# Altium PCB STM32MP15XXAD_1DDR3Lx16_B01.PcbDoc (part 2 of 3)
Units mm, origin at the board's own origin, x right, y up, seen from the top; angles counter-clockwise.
Board outline 86 x 120 mm, 4 copper layers (Top Layer, Signal Layer 1, Signal Layer 2, Bottom Layer), stack 1.571 mm thick; 118 components, 119 nets, 781 pads, 336 vias.
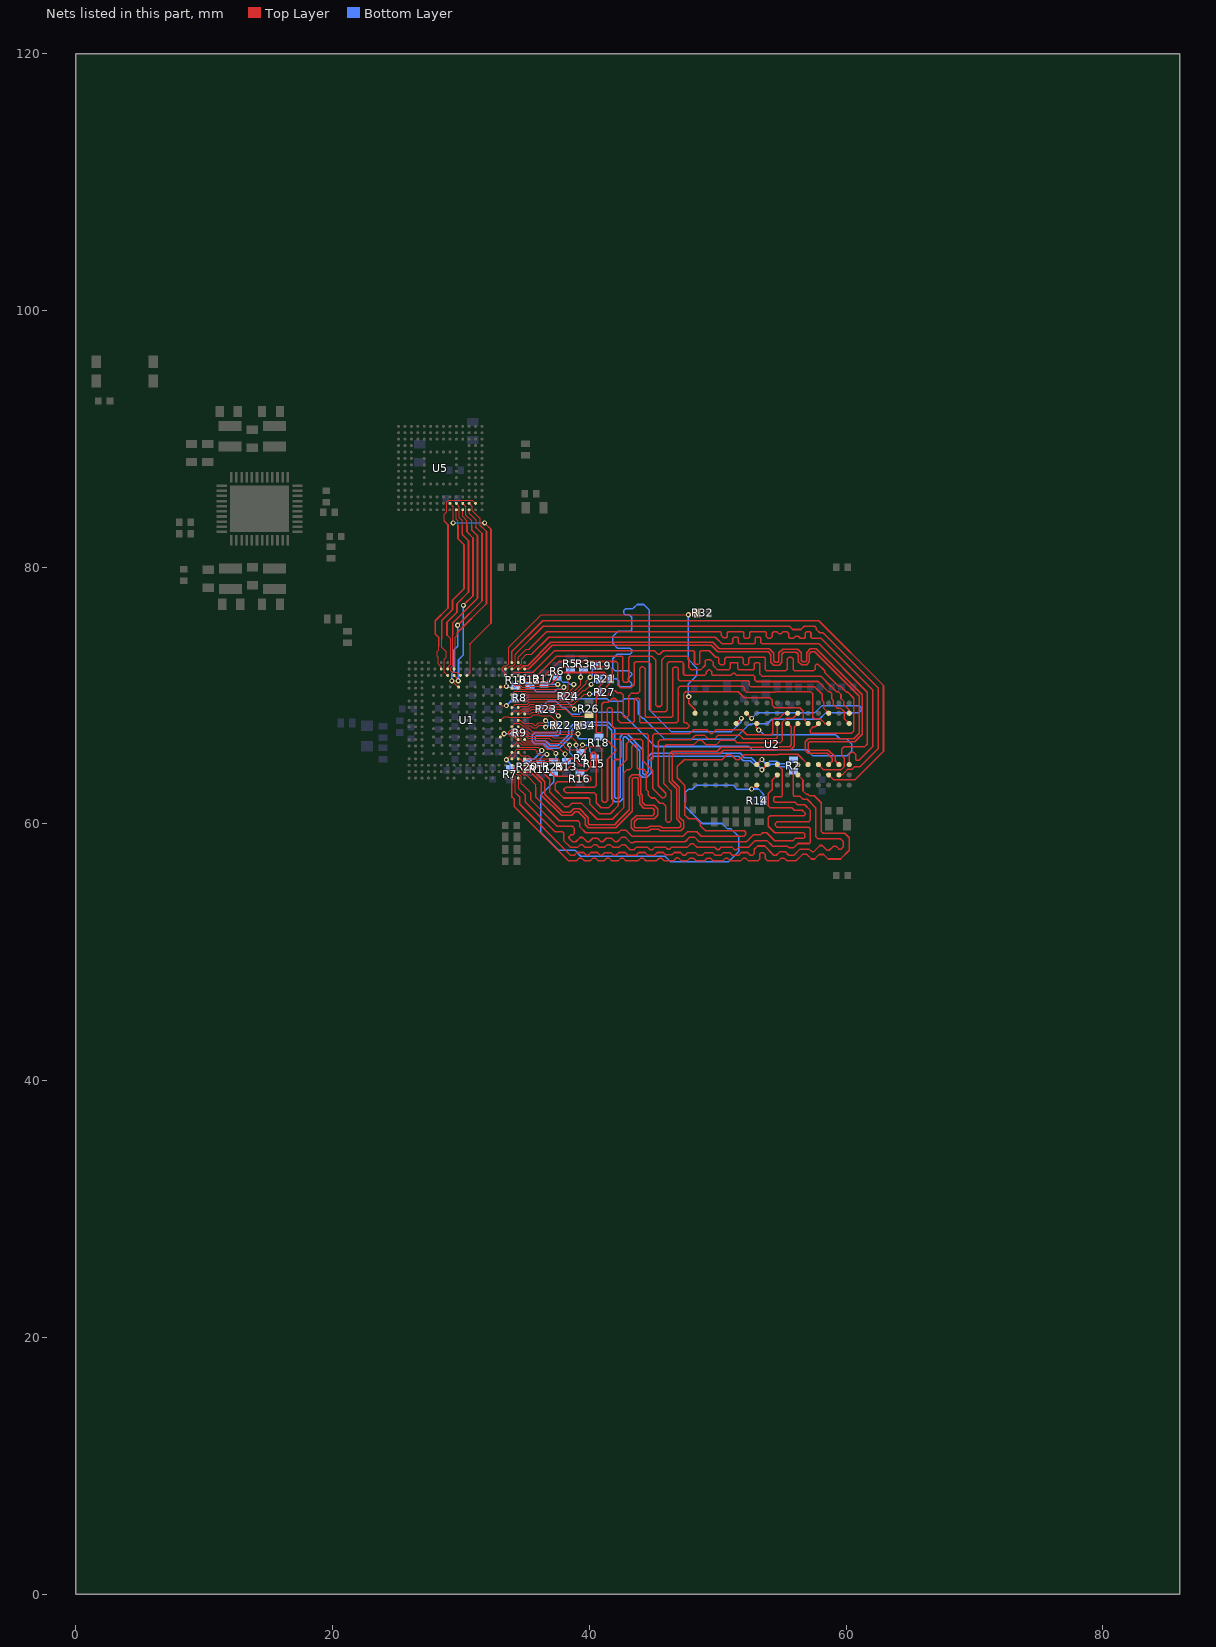
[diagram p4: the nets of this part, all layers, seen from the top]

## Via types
v1: diameter 0.4, hole 0.2, Top Layer to Bottom Layer, tented both sides, 260 vias
v2: diameter 0.6, hole 0.3, Top Layer to Bottom Layer, tented both sides, 74 vias
v3: diameter 0.4, hole 0.2, Top Layer to Signal Layer 1, tented top, 2 vias

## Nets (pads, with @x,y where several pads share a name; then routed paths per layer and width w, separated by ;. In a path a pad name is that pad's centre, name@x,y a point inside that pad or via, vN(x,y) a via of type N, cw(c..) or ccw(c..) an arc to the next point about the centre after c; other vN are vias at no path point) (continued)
BA2: R21.2 U2.M3 | length 32.5
  Top Layer w0.12: U2.M3@51.45,67.825 v1@51.83,68.205
  Bottom Layer w0.12: R21.2@41.675,71.3 42.15,71.3 42.3,71.15 42.3,70.82 42.425,70.695 43.201,70.695 43.305,70.799 43.305,70.945 43.05,71.2 43.05,71.35 43.305,71.605 43.305,71.72 43.1,71.925 42,71.925 41.825,72.1 41.825,72.869 42.176,73.22 43.175,73.22 43.305,73.35 43.305,73.57 43.2,73.675 42.226,73.675 41.825,74.076 41.825,74.594 42.226,74.995 43.175,74.995 43.305,75.125 43.305,76.1 43.11,76.295 42.805,76.295 42.7,76.4 42.7,76.65 42.8,76.75 43.375,76.75 43.5,76.875 ; 43.503,76.872 43.726,77.095 44.249,77.095 44.66,76.684 44.66,68.915 46.38,67.195 47.823,67.195 47.828,67.2 51.085,67.2 51.85,67.965 v1(51.85,68.225)
CASN: R23.2 U2.K3 | length 35.4
  Top Layer w0.12: U2.K3@53.05,67.825 53.025,67.8 53.025,67.5 v1@53.2,67.325
  Bottom Layer w0.12: R23.2@36.2,68.95 36.2,68.975 36.8,69.575 37.4,69.575 37.938,69.037 38.137,69.037 38.585,68.59 38.645,68.53 39.181,68.53 39.362,68.714 39.368,68.72 42.455,68.72 42.55,68.625 45.14,66.035 52.44,66.035 52.685,65.79 56.935,65.79 57.395,65.33 60.099,65.33 60.445,65.676 60.445,66.23 60.03,66.645 59.505,66.645 59.275,66.875 59.185,66.965 53.585,66.965 53.225,67.325 53.205,67.325 v1(53.2,67.32)
CKE: R14.2 R25.2 U2.K9 | length 36.9
  Top Layer w0.09: v1(52.65,62.725) 52.7,62.725 U2.K9@53,63.025
  Top Layer w0.1: U2.K9@53.05,63.025 U2.K9@53.075,63.025
  Top Layer w0.12: U2.K9@53,63.025 U2.K9@53.05,63.025
  Bottom Layer w0.12: R25.2@37.225,64 37.225,63.257 36.225,62.257 36.225,59.337 37.624,57.939 38.906,57.939 39.349,57.495 45.904,57.495 46.324,57.075 50.863,57.075 51.64,57.852 51.64,59.023 51.048,59.615 50.767,59.615 50.342,60.04 48.802,60.04 47.45,61.392 47.45,62.434 47.726,62.71 48.032,62.71 48.357,63.035 51.19,63.035 51.512,62.713 52.637,62.713 v1(52.65,62.725) 53.175,62.725 53.575,62.325 53.575,61.825 R14.2@53.575,61.775
CSN: R24.2 U2.L2 | length 35.3
  Top Layer w0.12: U2.L2@52.25,68.625 v1(52.65,68.225)
  Bottom Layer w0.12: R24.2@38.775,69.95 R24.2@38.8,69.95 38.875,69.95 39.075,69.75 41.384,69.75 41.574,69.56 42.56,69.56 42.75,69.75 43.6,69.75 43.805,69.545 43.805,68.576 44.153,68.228 ; 44.15,68.225 44.25,68.225 45.86,66.615 51.315,66.615 52.45,67.75 52.675,67.75 52.725,67.8 53.875,67.8 54.225,68.15 57.925,68.15 58.45,68.675 61.025,68.675 61.175,68.825 61.175,69.1 61.05,69.225 58.125,69.225 57.55,68.65 53.075,68.65 v1(52.65,68.225)
DDR_A0: R3.1 U1.G18 | length 6.7
  Top Layer w0.09: U1.G18@34.46,69.58 34.465,69.585 34.705,69.825 35.125,69.825 35.205,69.905 38.38,69.905 39.325,70.85 v1(39.325,71.425)
  Bottom Layer w0.12: v1(39.325,71.425) 39.325,71.8 R3.1@39.55,72.025
DDR_A1: R4.1 U1.M19 | length 5.3
  Top Layer w0.09: U1.M19@34.975,67.075 35.075,67.075 35.3,66.85 37.1,66.85 37.225,66.725 38.675,66.725 38.975,66.425 v1(38.975,66.15)
  Bottom Layer w0.12: v1(38.975,66.15) 38.975,65.95 39.363,65.563 R4.1@39.375,65.55
DDR_A2: R5.1 U1.F17 | length 6.2
  Top Layer w0.09: U1.F17@33.96,70.08 33.965,70.085 34.2,70.32 35.076,70.32 35.096,70.3 37.865,70.3 ; 37.875,70.3 38.163,70.3 38.37,70.507 v1@38.37,71.425
  Bottom Layer w0.12: v1@38.35,71.425 38.362,71.438 38.375,71.45 38.375,71.9 R5.1@38.525,72.05
  other v1: 38.375,71.425
DDR_A3: R6.1 U1.F19 | length 5.8
  Top Layer w0.09: U1.F19@34.99,70.1 34.995,70.095 35.015,70.075 38.24,70.075 38.8,70.635 v1(38.8,70.875) v1@38.8,70.9
  Bottom Layer w0.12: R6.1@37.525,71.45 37.925,71.05 38.325,71.05 38.5,70.875 v1(38.8,70.875)
DDR_A4: R7.1 U1.R17 | length 1.6
  Top Layer w0.09: v1(33.55,65) 33.975,65.425 U1.R17@33.975,65.575
  Bottom Layer w0.1: R7.1@33.8,64.375 R7.1@33.85,64.325
  Bottom Layer w0.12: v1(33.55,65) 33.85,64.7 R7.1@33.85,64.325
DDR_A5: R8.1 U1.1C9 | length 1.5
  Top Layer w0.09: U1.1C9@33.075,69.375 33.225,69.225 v1(33.55,69.225)
  Top Layer w0.1: v1@33.45,69.325 v1(33.55,69.225)
  Bottom Layer w0.1: v1(33.55,69.225) R8.1@34.15,69.825
DDR_A6: R9.1 U1.1G9 | length 1.2
  Top Layer w0.09: U1.1G9@33.125,66.725 33.125,66.775 v1(33.375,67.025)
  Bottom Layer w0.1: v1(33.375,67.025) R9.1@34.15,67.025
DDR_A7: R10.1 U1.1A9 | length 1.3
  Top Layer w0.09: U1.1A9@33.075,70.675 33.5,70.675 v1(33.55,70.725)
  Bottom Layer w0.12: v1(33.55,70.725) 33.625,70.65 34.2,70.65 R10.1@34.3,70.75
DDR_A8: R11.1 U1.T17 | length 4.6
  Top Layer w0.09: U1.T17@33.975,65.075 34.222,65.322 34.222,65.678 34.364,65.82 35.743,65.82 35.945,65.618 35.945,65.48 36.045,65.38 36.655,65.38 v1(36.7,65.425)
  Bottom Layer w0.12: R11.1@36.2,64.7 36.2,65.1 36.525,65.425 v1(36.7,65.425)
DDR_A9: R12.1 U1.E18 | length 6.7
  Top Layer w0.09: U1.E18@34.46,70.58 34.475,70.58 34.633,70.58 34.723,70.49 37.865,70.49 v1(38.025,70.65)
  Bottom Layer w0.12: R12.1@35.4,70.8 35.9,70.3 37.3,70.3 37.5,70.5 37.875,70.5 v1(38.025,70.65) v1@38.05,70.675
DDR_A10: R13.1 U1.M17 | length 5.6
  Top Layer w0.09: U1.M17@33.97,67.08 33.975,67.08 34.116,67.08 34.366,66.83 34.585,66.83 34.72,66.695 34.72,66.484 34.874,66.33 36.545,66.33 36.8,66.075 37.5,66.075 v1@38.112,65.463 ; v1@38.031,65.556 38.088,65.5 v1@38.1,65.5
  Bottom Layer w0.12: v1(38.125,65.45) 38.125,65.025 R13.1@38.25,64.9
DDR_A11: R15.1 U1.N19 | length 6.6
  Top Layer w0.09: U1.N19@34.97,66.58 U1.N19@34.975,66.575 35.05,66.5 36.55,66.5 ; 36.555,66.5 36.7,66.5 36.925,66.275 37.813,66.275 38.288,65.8 39.175,65.8 39.45,66.075 v1@39.45,66.125
  Bottom Layer w0.12: v1(39.475,66.15) 39.825,66.15 40.03,65.945 40.03,65.676 40.4,65.306 R15.1@40.4,65.15 R15.1@40.4,65.125
DDR_A12: R16.1 U1.M18 | length 6.8
  Top Layer w0.09: U1.M18@34.47,67.08 34.475,67.08 34.624,67.08 34.884,66.82 35.08,66.82 35.225,66.675 36.9,66.675 37.075,66.5 38.125,66.5 v1(38.475,66.15) v1@38.5,66.125
  Bottom Layer w0.12: v1(38.475,66.15) 38.475,65.575 38.825,65.225 38.825,64.35 R16.1@39.15,64.025
DDR_A13: R17.1 U1.E17 | length 5
  Top Layer w0.09: U1.E17@33.96,70.58 33.965,70.585 34.205,70.825 34.628,70.825 34.793,70.66 35.385,70.66 35.45,70.725 37.4,70.725 v1(37.55,70.875)
  Bottom Layer w0.12: R17.1@36.5,70.875 v1(37.55,70.875) 37.585,70.875 v1@37.6,70.89
DDR_A14: R18.1 U1.N18 | length 8.7
  Top Layer w0.09: U1.N18@34.47,66.58 34.34,66.58 34.09,66.83 33.865,66.83 33.72,66.975 33.72,67.19 33.85,67.32 34.576,67.32 34.621,67.275 34.829,67.275 34.874,67.32 35.076,67.32 35.371,67.025 37.35,67.025 37.4,66.975 38.775,66.975 38.825,67.025 v1(39.125,67.025)
  Bottom Layer w0.12: v1(39.125,67.025) 39.125,66.725 39.2,66.65 R18.1@40.725,66.65
DDR_A15: R34.1 U1.L18 | length 5.2
  Top Layer w0.09: U1.L18@34.475,67.575 34.56,67.49 35.285,67.49 ; 35.295,67.48 35.575,67.2 38.725,67.2 38.813,67.288 38.813,67.588 38.9,67.675 R34.1@39.2,67.675
DDR_BA0: R19.1 U1.G19 | length 7
  Top Layer w0.09: U1.G19@34.96,69.58 34.975,69.58 35.18,69.58 35.325,69.725 38.525,69.725 39.75,70.95 39.75,71.1 v1(40.075,71.425)
  Bottom Layer w0.12: v1(40.075,71.425) 40.25,71.6 40.25,72.075 40.45,72.275 R19.1@40.45,72.325
DDR_BA1: R20.1 U1.P18 | length 3.5
  Top Layer w0.09: U1.P18@34.47,66.08 U1.P18@34.475,66.075 34.56,65.99 36.035,65.99 v1(36.3,65.725)
  Bottom Layer w0.12: R20.1@35.2,64.9 35.35,65.05 35.684,65.05 36.3,65.666 v1(36.3,65.725)
DDR_BA2: R21.1 U1.H17 | length 7.7
  Top Layer w0.09: U1.H17@33.975,69.075 34.23,69.33 35.17,69.33 35.365,69.525 38.65,69.525 39.525,70.4 39.7,70.4 40.125,70.825 v1@40.125,70.875
  Bottom Layer w0.12: v1@40.15,70.9 40.35,71.1 40.575,71.1 R21.1@40.775,71.3
  other v1: 40.15,70.875
DDR_CASN: R23.1 U1.J19 | length 3.6
  Top Layer w0.09: U1.J19@34.97,68.58 34.975,68.58 35.405,68.58 35.545,68.72 37.355,68.72 37.6,68.475 v1(37.6,68.425)
  Bottom Layer w0.12: R23.1@37.1,68.95 37.1,68.925 v1(37.6,68.425)
DDR_CKE: R25.1 U1.P17 | length 4.6
  Top Layer w0.09: U1.P17@33.95,66.08 33.975,66.08 34.116,66.08 34.366,66.33 34.595,66.33 34.765,66.16 36.365,66.16 36.7,65.825 37.075,65.825 v1(37.4,65.5)
  Bottom Layer w0.12: R25.1@37.225,64.875 R25.1@37.225,64.9 37.4,65.075 v1(37.4,65.5)
DDR_CLK_N: R2.1 U1.K18 U2.K7 | length 43.4
  Top Layer w0.09: U1.K18@34.475,68.075 34.625,68.075 34.87,67.83 35.57,67.83 35.7,67.7 35.856,67.7 36.046,67.89 36.44,67.89 v1(36.6,68.05)
  Top Layer w0.1: U2.K7@53.05,64.625 v1(53.45,65.025)
  Bottom Layer w0.1: v1(36.6,68.05) 36.675,68.05 36.82,67.905 37.52,67.905 37.755,67.67 37.755,67.08 37.55,66.875 35.85,66.875 35.78,66.805 35.78,66.545 35.845,66.48 36.57,66.48 36.91,66.14 37.59,66.14 38.42,66.97 38.42,67.395 38.775,67.75 39.55,67.75 39.73,67.93 41.47,67.93 42,67.4 42,62.075 42.07,62.005 42.305,62.005 42.4,62.1 42.4,66.8 42.63,67.03 42.945,67.03 44.175,65.8 44.175,63.95 44.27,63.855 44.38,63.855 44.61,64.085 44.61,65.235 44.88,65.505 51.745,65.505 52.088,65.163 52.637,65.163 53.05,64.75 53.175,64.75 v1(53.45,65.025) 53.725,64.75 53.925,64.75 54.05,64.875 54.625,64.875 54.825,64.675 55.5,64.675 R2.1@55.825,65
DDR_CLK_P: R2.2 U1.L17 U2.J7 | length 44.1
  Top Layer w0.09: U1.L17@33.97,67.58 34.22,67.83 34.601,67.83 34.771,67.66 35.45,67.66 35.61,67.5 35.925,67.5 36.125,67.7 36.45,67.7 v1(36.6,67.55)
  Top Layer w0.1: v1(53.45,64.225) U2.J7@53.85,64.625
  Bottom Layer w0.1: v1(36.6,67.55) 36.7,67.55 36.825,67.675 37.425,67.675 37.525,67.575 37.525,67.175 37.455,67.105 35.755,67.105 35.55,66.9 35.55,66.45 35.75,66.25 36.475,66.25 36.815,65.91 37.685,65.91 38.65,66.875 38.65,67.3 38.87,67.52 39.645,67.52 39.825,67.7 41.375,67.7 41.77,67.305 41.77,61.98 42,61.75 42.375,61.75 42.65,62.025 42.65,66.725 42.725,66.8 42.85,66.8 43.945,65.705 43.945,63.855 44.175,63.625 44.475,63.625 44.84,63.99 44.84,65.14 44.975,65.275 51.65,65.275 52,64.925 52.55,64.925 52.955,64.52 53.155,64.52 v1(53.45,64.225) 53.48,64.225 53.775,64.52 54.02,64.52 54.145,64.645 54.53,64.645 54.73,64.445 55,64.445 55.48,64.445 R2.2@55.825,64.1 ; R2.2@55.925,64.1 R2.2@55.925,64.175
DDR_CSN: R24.1 U1.J17 | length 6.6
  Top Layer w0.09: U1.J17@33.97,68.58 U1.J17@33.975,68.575 34.22,68.82 34.633,68.82 34.803,68.99 35.334,68.99 35.469,69.125 38.675,69.125 v1(38.85,68.95)
  Bottom Layer w0.12: R24.1@37.875,69.925 v1(38.85,68.95)
DDR_DQ0: U1.A17 U2.C8 | length 43.3
  Top Layer w0.12: U1.A17@33.975,72.575 33.975,73.425 36.375,75.825 57.877,75.825 62.92,70.782 62.92,65.67 60.7,63.45 59.025,63.45 U2.C8@58.65,63.825
DDR_DQ1: U1.A18 U2.A7 | length 42.3
  Top Layer w0.09: U1.A18@34.47,72.58 34.47,72.995 35.1,73.625 35.325,73.625
  Top Layer w0.12: 35.33,73.63 36.675,74.975 50.2,74.975 50.3,74.875 50.3,74.669 50.469,74.5 50.675,74.5 50.75,74.575 50.75,74.9 50.825,74.975 51.975,74.975 52.05,74.9 52.05,74.55 52.125,74.475 52.4,74.475 52.5,74.575 52.5,74.85 52.5,74.9 52.575,74.975 53.725,74.975 53.8,74.9 53.8,74.6 53.925,74.475 54.125,74.475 54.25,74.6 54.25,74.85 54.375,74.975 54.6,74.975 54.775,74.8 54.925,74.8 55.1,74.975 55.4,74.975 55.55,74.825 55.55,74.55 55.63,74.47 55.92,74.47 56.075,74.625 56.275,74.625 56.43,74.47 56.745,74.47 56.825,74.55 56.825,74.875 56.925,74.975 57.2,74.975 57.275,74.9 57.275,74.55 57.355,74.47 58.044,74.47 62.08,70.434 62.08,66.036 61.014,64.97 60.805,64.97 60.75,65.025 60.75,65.425 60.6,65.575 60.4,65.575 60.25,65.425 60.25,65.298 ; U2.A7@60.25,64.6 U2.A7@60.25,64.625 60.25,65.3
DDR_DQ2: U1.C18 U2.A3 | length 41.6
  Top Layer w0.09: U1.C18@34.47,71.58 U1.C18@34.475,71.575 34.72,71.33 36.315,71.33
  Top Layer w0.12: 36.329,71.346 37.638,72.655 42.095,72.655 42.205,72.545 42.205,70.845 42.425,70.625 43.275,70.625 43.5,70.85 43.5,72.525 43.625,72.65 44.625,72.65 44.78,72.495 44.78,68.87 44.925,68.725 45.925,68.725 46.07,68.87 46.07,72.495 46.225,72.65 47.225,72.65 47.345,72.53 47.345,71.655 47.425,71.575 48.975,71.575 49.1,71.7 49.1,71.825 49.275,72 49.4,72 49.55,71.85 49.55,71.65 49.625,71.575 50.025,71.575 51.025,71.575 51.2,71.75 51.325,71.75 51.5,71.575 52.8,71.575 52.899,71.476 52.899,71.226 53.025,71.1 57.831,71.1 58.646,70.285 58.765,70.285 ; 58.775,70.275 58.885,70.165 58.885,69.74 59.012,69.613 59.012,69.313 59.3,69.025 59.58,69.025 59.86,68.745 59.86,68.215 60.19,67.885 U2.A3@60.19,67.825
DDR_DQ3: U1.B16 U2.B8 | length 41.9
  Top Layer w0.09: U1.B16@33.47,72.08 33.475,72.08 33.55,72.08 33.55,72.106 33.528,72.128 33.52,72.136 33.661,72.136 33.845,72.32 34.076,72.32 34.078,72.318 34.225,72.465 34.225,73.2 34.3,73.275
  Top Layer w0.12: 34.3,73.275 36.425,75.4 55.6,75.4 55.85,75.15 56.5,75.15 56.75,75.4 57.575,75.4 57.7,75.275 57.7,75.15 57.95,74.9 58.175,74.9 ; 58.1,74.9 58.208,74.9 62.5,70.608 62.5,65.862 61.113,64.475 60.675,64.475 60.455,64.255 60.115,64.255 59.685,63.825 U2.B8@59.45,63.825
DDR_DQ4: U1.D18 U2.C3 | length 43.1
  Top Layer w0.09: U1.D18@34.47,71.08 34.475,71.08 34.614,71.08 34.864,70.83 35.155,70.83 35.25,70.925 37.075,70.925
  Top Layer w0.12: 37.075,70.95 37.925,71.8 41.2,71.8 41.35,71.65 41.35,71.275 40.55,70.475 40.55,67.175 40.625,67.1 40.9,67.1 40.975,67.175 40.975,69.325 41.125,69.475 41.5,69.475 41.8,69.775 42.025,69.775 42.23,69.57 42.23,68.095 42.45,67.875 43.375,67.875 43.5,68 43.5,69.7 43.575,69.775 43.85,69.775 43.925,69.7 43.925,67.975 44.02,67.88 46.805,67.88 46.925,68 46.925,68.688 46.925,70.575 47.075,70.725 51.975,70.725 52.059,70.641 52.059,70.441 52.25,70.25 54.475,70.25 54.51,70.285 57.265,70.285 57.41,70.14 57.41,68.315 57.525,68.2 57.984,68.2 58.359,67.825 U2.C3@58.65,67.825
DDR_DQ5: U1.D19 U2.C2 | length 43.4
  Top Layer w0.09: U1.D19@34.97,71.08 34.99,71.1 36.7,71.1
  Top Layer w0.12: 36.715,71.115 37.835,72.235 41.615,72.235 41.785,72.065 41.785,71.11 40.97,70.295 40.97,70.005 41.07,69.905 41.305,69.905 41.525,70.125 41.775,70.375 42.019,70.375 42.189,70.205 42.495,70.205 42.65,70.05 42.65,68.4 42.755,68.295 42.92,68.295 43.075,68.45 43.075,69.975 43.3,70.2 ; 43.306,70.206 43.3,70.2 ; 52.6,70.675 52.595,70.68 ; 57.42,70.68 57.425,70.68 ; U2.C2@58.65,68.625 58.25,69.025 58.25,69.525 58.15,69.625 58.15,70.1 57.57,70.68 57.358,70.68 52.595,70.68 ; 43.3,70.2 43.8,70.2 43.92,70.32 43.92,72.1 44.05,72.23 44.22,72.23 44.36,72.09 44.36,68.39 44.45,68.3 46.4,68.3 46.5,68.4 46.5,72.125 46.6,72.225 46.825,72.225 46.925,72.125 46.925,71.275 47.05,71.15 52.4,71.15 52.479,71.071 52.479,70.796 52.595,70.68
DDR_DQ6: U1.C19 U2.A2 | length 43.1
  Top Layer w0.09: U1.C19@34.96,71.58 34.975,71.58 35.98,71.58
  Top Layer w0.12: 35.982,71.593 37.464,73.075 42.55,73.075 42.625,73 42.625,71.15 42.73,71.045 42.97,71.045 43.075,71.15 43.075,71.425 ; 43.075,71.43 43.075,71.65 ; 43.075,71.655 43.075,72.875 ; 43.075,72.8 43.075,72.95 43.205,73.08 44.87,73.08 45.2,72.75 45.2,69.25 45.3,69.15 45.55,69.15 45.65,69.25 45.65,72.775 45.95,73.075 47.625,73.075 47.765,72.935 47.765,72.185 47.95,72 48.675,72 49.045,72.37 49.045,72.72 49.1,72.775 49.475,72.775 49.675,72.575 49.675,72.325 50,72 50.85,72 50.975,72.125 50.975,72.525 51.024,72.574 51.526,72.574 51.58,72.52 51.58,72.095 51.675,72 52.775,72 52.851,72.076 52.851,72.476 52.949,72.574 53.226,72.574 53.3,72.5 53.3,71.675 53.45,71.525 57.725,71.525 58.025,71.525 58.82,70.73 58.823,70.73 59.222,70.331 59.268,70.285 59.415,70.285 59.61,70.09 59.61,69.774 59.84,69.544 59.84,69.285 60.25,68.875 U2.A2@60.25,68.625
DDR_DQ7: U1.B17 U2.D7 | length 42.2
  Top Layer w0.09: U1.B17@33.97,72.08 33.975,72.08 34.115,72.08 34.365,72.33 34.58,72.33 34.73,72.48 34.73,72.843 35.112,73.225 35.5,73.225
  Top Layer w0.12: 35.525,73.231 36.844,74.55 49.825,74.55 50.325,74.05 51.1,74.05 51.175,74.125 51.175,74.45 51.275,74.55 51.55,74.55 51.625,74.475 51.625,74.125 51.7,74.05 52.85,74.05 52.925,74.125 52.925,74.475 53,74.55 53.3,74.55 53.375,74.475 53.375,74.125 53.45,74.05 57.87,74.05 61.66,70.26 61.66,66.21 61.45,66 59.825,66 59.675,65.85 59.675,65.325 59.83,65.17 ; U2.D7@57.85,64.625 58.26,64.215 59.62,64.215 59.85,64.445 59.85,65.17
DDR_DQ8: U1.R18 U2.E3 | length 43.4
  Top Layer w0.09: U1.R18@34.475,65.575 34.725,65.325 35.25,65.325 35.5,65.075 37.575,65.075 37.675,64.975
  Top Layer w0.12: 37.675,64.975 37.675,64.769 37.874,64.57 38,64.57 38.53,65.1 38.8,65.1 39.325,64.575 39.625,64.575 39.7,64.65 39.7,64.9 39.45,65.15 39.45,65.375 39.7,65.625 39.7,65.825 39.875,66 40.825,66 40.975,65.85 40.975,61.844 41.119,61.7 41.3,61.7 41.425,61.825 41.425,65.05 42.065,65.69 42.065,65.86 41.725,66.2 ; 41.75,66.175 41.4,66.525 41.4,68.95 41.505,69.055 41.705,69.055 41.81,68.95 41.81,67.59 41.95,67.45 47.637,67.45 47.775,67.588 47.775,67.7 47.6,67.875 47.425,67.875 47.35,67.95 47.35,68.519 47.35,70.125 47.525,70.3 51.6,70.3 52.075,69.825 54.08,69.825 54.24,69.665 54.24,69.26 54.445,69.055 56.395,69.055 56.665,68.785 56.665,68.21 U2.E3@57.05,67.825
DDR_DQ9: U1.U19 U2.F2 | length 42.9
  Top Layer w0.09: U1.U19@34.97,64.58 U1.U19@34.975,64.575 35.15,64.575 35.25,64.475 35.95,64.475 36.275,64.15
  Top Layer w0.12: 36.275,64.15 36.935,63.49 36.935,62.499 38.104,61.329 38.374,61.329 38.645,61.6 39.4,61.6 40.625,60.375 41.8,60.375 42.7,61.275 42.7,64 42.936,64.236 43.161,64.236 43.325,64.4 43.325,66.05 43.386,66.111 43.386,66.117 43.444,66.175 43.6,66.175 43.75,66.025 43.75,64.375 43.865,64.26 44.24,64.26 44.45,64.05 44.45,62.684 44.615,62.519 44.615,62.235 44.825,62.025 45.106,62.025 45.166,61.966 ; 45.163,61.962 45.5,61.625 45.75,61.625 45.95,61.425 45.95,60.275 46.1,60.125 46.225,60.125 46.375,60.275 46.375,62.575 45.8,63.15 45.8,66 45.955,66.155 48.13,66.155 48.48,66.505 48.77,66.505 49.12,66.155 49.875,66.155 50.225,66.505 51.34,66.505 51.53,66.315 54.865,66.315 55.05,66.5 55.05,67.934 55.341,68.225 55.85,68.225 U2.F2@56.25,68.625
DDR_DQ10: U1.T19 U2.G2 | length 43.2
  Top Layer w0.09: U1.T19@34.97,65.08 34.975,65.08 35.2,65.08 35.405,64.875 36.975,64.875
  Top Layer w0.12: 36.988,64.863 37.7,64.15 38.175,64.15 38.525,64.5 38.806,64.5 39.156,64.15 39.794,64.15 40.125,64.481 40.125,65.43 40.275,65.58 40.4,65.58 40.55,65.43 40.55,63 40.425,62.875 38.2,62.875 38.025,62.7 38.025,62.6 38.175,62.45 40.375,62.45 40.55,62.275 40.55,61.65 40.938,61.263 40.95,61.25 41.475,61.25 41.85,61.625 41.85,64.875 42,65.025 42.325,65.025 42.485,65.185 42.485,66.49 42.375,66.6 41.95,66.6 41.82,66.73 41.82,66.955 41.895,67.03 44.495,67.03 44.6,66.925 44.6,65.094 44.719,64.975 44.85,64.975 44.95,65.075 44.95,65.325 ; 44.95,65.33 44.95,66.9 45.08,67.03 47.811,67.03 48.126,67.345 49.149,67.345 49.449,67.045 49.577,67.045 49.877,67.345 51.88,67.345 52.27,66.955 54.18,66.955 54.29,67.065 54.29,68.09 54.425,68.225 54.775,68.225 55.175,68.625 U2.G2@55.45,68.625
DDR_DQ11: U1.W18 U2.H7 | length 42.8
  Top Layer w0.09: U1.W18@34.47,63.58 34.47,63.575 34.47,63.525 34.476,62.794 34.8,62.475
  Top Layer w0.12: 34.795,62.487 35.003,62.278 35.003,61.734 ; 35.003,61.728 37.326,59.405 37.895,59.405 38,59.3 38,58.725 38.525,58.2 39.125,58.2 39.325,58.4 39.45,58.4 39.65,58.2 40.175,58.2 40.375,58.4 40.55,58.4 40.75,58.2 41.219,58.2 41.419,58.4 41.625,58.4 41.825,58.2 42.344,58.2 42.544,58.4 42.775,58.4 43.18,57.995 43.482,57.995 43.687,58.2 44.525,58.2 44.725,58 44.925,58 45.125,58.2 45.95,58.2 46.125,58.025 46.262,58.025 46.437,58.2 47.65,58.2 47.9,58.45 48.125,58.45 48.385,58.19 49.773,58.19 49.968,57.995 50.082,57.995 50.287,58.2 51.113,58.2 51.318,57.995 51.47,57.995 51.675,58.2 52.425,58.2 52.93,58.705 53.845,58.705 54.175,58.375 ; 54.175,58.369 54.175,58.375 ; U2.H7@54.65,64.625 55.05,64.225 55.05,62.225 54.95,62.125 54.45,62.125 54.375,62.05 54.375,61.9 54.375,61.8 54.48,61.695 56.03,61.695 56.225,61.5 56.35,61.5 ; 56.355,61.5 56.781,61.5 57.23,61.051 57.23,60.305 57.1,60.175 54.625,60.175 54.5,60.05 54.5,59.875 54.625,59.75 57.1,59.75 57.225,59.625 57.225,58.55 57.155,58.48 56.255,58.48 56.1,58.325 56.1,58.319 55.941,58.159 55.559,58.159 55.444,58.275 54.275,58.275 54.175,58.375
DDR_DQ12: U1.W17 U2.F8 | length 42.9
  Top Layer w0.09: U1.W17@33.97,63.575 U1.W17@33.97,63.58
  Top Layer w0.12: U1.W17@33.975,63.575 33.975,62.125 34.15,61.95 ; 34.125,61.969 34.164,61.93 34.164,61.362 ; 34.25,61.275 34.164,61.362 ; U2.F8@56.25,63.825 56.65,63.425 56.65,62.575 56.925,62.3 57.05,62.3 57.15,62.2 57.525,62.2 58.075,61.65 58.075,59.425 58.225,59.275 59.9,59.275 60.25,58.925 60.25,57.95 59.575,57.275 58.6,57.275 58.25,57.625 57.9,57.625 57.55,57.275 57.306,57.275 56.951,57.63 56.605,57.63 56.125,57.15 55.381,57.15 55.181,57.35 54.95,57.35 54.75,57.15 53.875,57.15 53.7,57.325 53.7,57.625 53.55,57.775 53.375,57.775 53.275,57.675 53.275,57.275 53.15,57.15 52.375,57.15 52.175,57.35 52.013,57.35 51.813,57.15 50.975,57.15 50.775,57.35 50.625,57.35 50.43,57.155 49.62,57.155 49.425,57.35 49.2,57.35 49,57.15 48.3,57.15 48.1,57.35 47.85,57.35 47.65,57.15 47.156,57.15 46.946,57.36 46.785,57.36 46.559,57.134 45.822,57.134 45.621,57.335 45.448,57.335 45.248,57.135 44.396,57.135 44.181,57.35 44.025,57.35 43.825,57.15 42.825,57.15 42.625,57.35 42.475,57.35 42.275,57.15 41.731,57.15 41.531,57.35 41.375,57.35 41.18,57.155 40.676,57.155 40.481,57.35 40.3,57.35 40.1,57.15 39.606,57.15 39.406,57.35 39.225,57.35 39.025,57.15 38.375,57.15 34.164,61.361
DDR_DQ13: U1.T18 U2.H3 | length 43.4
  Top Layer w0.09: U1.T18@34.47,65.08 U1.T18@34.475,65.075 34.48,65.07 34.625,65.07 34.87,64.825 35.15,64.825 35.3,64.675 36.35,64.675 36.65,64.375
  Top Layer w0.12: 36.65,64.375 37.3,63.725 40.025,63.725 40.13,63.62 40.13,63.405 40.025,63.3 37.525,63.3 37.355,63.13 37.355,62.673 38.003,62.025 39.975,62.025 40.05,61.95 40.05,61.556 40.801,60.805 41.63,60.805 42.275,61.45 42.275,64.375 42.905,65.005 42.905,66.255 43.25,66.6 44.025,66.6 44.18,66.445 44.18,64.92 44.95,64.15 44.95,62.778 45.035,62.693 45.035,62.69 45.675,62.05 45.825,62.05 45.955,62.18 45.955,62.395 45.375,62.975 45.375,66.425 45.525,66.575 47.95,66.575 48.3,66.925 48.975,66.925 49.275,66.625 49.751,66.625 50.051,66.925 51.706,66.925 51.996,66.635 54.56,66.635 54.65,66.725 U2.H3@54.65,67.825
DDR_DQ14: U1.U17 U2.H8 | length 42.4
  Top Layer w0.09: U1.U17@33.97,64.58 U1.U17@33.975,64.575 34.22,64.33 34.22,63.984 34.379,63.825 34.575,63.825 34.725,63.675 34.725,63.15 34.85,63.025
  Top Layer w0.12: 34.835,63.041 35.43,62.445 35.43,61.901 37.501,59.83 37.7,59.83 ; 37.5,59.825 38.675,59.825 38.85,59.65 38.85,59.275 38.725,59.15 38.575,59.15 38.425,59 38.425,58.894 38.694,58.625 38.956,58.625 39.281,58.95 39.494,58.95 39.819,58.625 40.006,58.625 40.276,58.895 40.655,58.895 40.925,58.625 41.05,58.625 41.32,58.895 41.73,58.895 42,58.625 42.175,58.625 42.506,58.956 42.825,58.956 43.253,58.528 43.422,58.528 43.518,58.625 47.475,58.625 ; 47.481,58.625 47.475,58.625 ; U2.H8@54.65,63.825 54.25,63.425 54.25,62.675 54.14,62.565 53.95,62.375 53.95,61.4 54.075,61.275 55.775,61.275 55.975,61.075 56.6,61.075 56.81,60.865 56.81,60.735 56.725,60.65 54.1,60.65 53.95,60.5 53.95,59.825 54.45,59.325 56.7,59.325 56.8,59.225 56.8,58.975 56.725,58.9 56.075,58.9 55.875,58.7 54.45,58.7 53.825,59.325 53.525,59.325 53.35,59.15 52.775,59.15 52.25,58.625 48.556,58.625 48.201,58.98 47.83,58.98 47.475,58.625
DDR_DQ15: U1.V17 U2.F7 | length 43.1
  Top Layer w0.09: U1.V17@33.97,64.08 33.97,64.075 33.97,63.926 34.225,63.671 34.225,62.45 34.4,62.275
  Top Layer w0.12: 34.395,62.293 34.583,62.104 34.583,61.541 38.55,57.575 38.85,57.575 39.055,57.78 39.57,57.78 39.775,57.575 39.931,57.575 40.136,57.78 40.645,57.78 40.85,57.575 41.006,57.575 41.206,57.775 41.7,57.775 41.9,57.575 42.106,57.575 42.311,57.78 42.801,57.78 43.006,57.575 43.656,57.575 43.861,57.78 44.345,57.78 44.57,57.555 45.074,57.555 45.299,57.78 45.77,57.78 45.95,57.6 46.431,57.6 46.611,57.78 47.12,57.78 47.325,57.575 47.481,57.575 47.676,57.77 48.28,57.77 48.475,57.575 48.825,57.575 49.02,57.77 49.599,57.77 49.794,57.575 50.256,57.575 50.456,57.775 50.944,57.775 51.144,57.575 51.644,57.575 51.849,57.78 52.339,57.78 52.544,57.575 52.725,57.575 52.85,57.7 52.85,58.025 53.11,58.285 53.665,58.285 54.375,57.575 54.575,57.575 54.855,57.855 55.27,57.855 55.55,57.575 55.95,57.575 56.425,58.05 57.125,58.05 57.325,57.85 57.5,57.85 57.975,58.325 58.15,58.325 58.525,57.95 58.7,57.95 59.025,58.275 59.225,58.275 59.45,58.05 59.625,58.05 59.8,58.225 59.8,58.625 59.575,58.85 57.825,58.85 57.65,59.025 57.65,61.25 56.975,61.925 56.65,61.925 56.425,62.15 55.975,62.15 55.875,62.25 55.875,64.25 U2.F7@56.25,64.625
DDR_DQM0: U1.C17 U2.D3 | length 43.1
  Top Layer w0.09: U1.C17@33.97,71.58 34.22,71.83 35.63,71.83
  Top Layer w0.12: 35.635,71.84 37.295,73.5 45.075,73.5 45.35,73.225 45.5,73.225 45.775,73.5 48.1,73.5 48.2,73.4 48.2,72.525 48.3,72.425 48.506,72.425 48.625,72.544 48.625,73.4 48.725,73.5 49.345,73.5 49.851,72.994 50.006,72.994 50.1,72.9 50.1,72.525 50.205,72.42 50.47,72.42 50.55,72.5 50.55,72.875 50.669,72.994 51.906,72.994 52,72.9 52,72.5 52.08,72.42 52.345,72.42 52.431,72.506 52.431,72.906 52.519,72.994 53.656,72.994 53.725,72.925 53.725,72.025 53.8,71.95 55.325,71.95 55.425,72.05 55.425,72.875 55.525,72.975 55.775,72.975 55.875,72.875 55.875,72.05 55.975,71.95 57.5,71.95 57.6,72.05 57.6,72.35 57.7,72.45 57.825,72.45 58.34,71.935 58.34,71.804 58.922,71.222 58.928,71.222 59.425,70.725 59.575,70.725 60.025,70.275 60.12,70.275 ; U2.D3@57.85,67.825 57.6,67.575 57.45,67.575 57.2,67.325 57.2,67.15 57.285,67.065 60.435,67.065 60.61,67.24 60.61,69.799 60.127,70.282
DDR_DQM1: U1.V18 U2.E7 | length 42
  Top Layer w0.09: U1.V18@34.47,64.08 34.475,64.08 34.624,64.08 34.879,63.825 35.1,63.825 35.85,63.075 35.85,62.875
  Top Layer w0.12: 35.85,62.875 35.85,62.075 37.675,60.25 39.1,60.25 39.275,60.075 39.275,59.775 39.735,59.315 42.265,59.315 42.475,59.525 42.85,59.525 43.325,59.05 47.3,59.05 ; 47.306,59.05 47.3,59.05 ; U2.E7@57.05,64.625 56.24,65.435 54.74,65.435 54.7,65.395 52.07,65.395 51.675,65 51.445,65 51.05,65.395 50.72,65.395 50.335,65.01 47.4,65.01 46.86,64.47 46.86,63.595 47.45,63.005 47.45,62.4 47.5,62.35 47.5,61.7 47.45,61.65 47.45,60.705 47.755,60.4 48.325,60.4 48.65,60.075 48.65,59.876 49.051,59.475 52.075,59.475 52.2,59.35 52.2,59.2 52.05,59.05 48.725,59.05 48.375,59.4 47.65,59.4 47.3,59.05
DDR_DQS0_N: U1.B18 U2.B7 | length 43.6
  Top Layer w0.1: U1.B18@34.47,72.08 34.475,72.08 34.616,72.08 34.861,72.325 35.2,72.325 ; 35.205,72.33 35.25,72.375 37.015,74.14 49.635,74.14 49.675,74.1 ; 49.638,74.138 50.141,73.634 54.041,73.634 54.38,73.295 54.38,72.695 54.485,72.59 54.69,72.59 54.775,72.675 54.775,73.325 55.075,73.625 56.225,73.625 56.525,73.325 56.525,72.75 56.645,72.63 56.83,72.63 56.925,72.725 56.925,73.35 57.205,73.63 57.67,73.63 61.25,70.064 61.25,66.975 60.7,66.425 57.175,66.425 57.075,66.325 57.075,65.825 57.145,65.755 58.62,65.755 59.155,65.22 59.155,64.92 U2.B7@59.45,64.625
DDR_DQS0_P: U1.B19 U2.C7 | length 42.6
  Top Layer w0.1: U1.B19@34.975,72.075 35.29,72.075 37.125,73.91 49.515,73.91 50.021,73.404 53.946,73.404 54.15,73.2 54.15,72.6 54.39,72.36 54.785,72.36 55.015,72.59 55.015,73.24 55.17,73.395 56.13,73.395 56.295,73.23 56.295,72.655 56.55,72.4 56.925,72.4 57.155,72.63 57.155,73.255 57.3,73.4 57.575,73.4 61.02,69.955 61.02,67.07 60.605,66.655 59.825,66.655 57.055,66.655 56.825,66.425 56.825,66.15 56.825,65.75 57.05,65.525 58.525,65.525 58.925,65.125 58.925,64.9 U2.C7@58.65,64.625
DDR_DQS1_N: U1.U18 U2.G3 | length 43.3
  Top Layer w0.1: U1.U18@34.47,64.58 U1.U18@34.475,64.575 34.725,64.325 35.079,64.325 35.094,64.31 35.129,64.275 35.55,64.275 36.525,63.3 36.525,62.329 37.949,60.905 38.53,60.905 38.8,61.175 39.245,61.175 39.93,60.49 39.93,60.045 40.02,59.955 41.98,59.955 42.229,60.205 43.125,61.1 43.125,63.6 43.355,63.83 43.82,63.83 44.03,63.62 44.03,62.37 44.15,62.25 44.15,61.675 44.35,61.475 45.05,61.475 45.325,61.2 45.325,60.7 45.05,60.425 43.75,60.425 43.505,60.18 43.505,59.795 43.6,59.7 44.475,59.7 44.575,59.7 44.7,59.825 45.55,59.825 45.67,59.705 45.888,59.705 45.893,59.7 46.65,59.7 46.975,59.7 46.988,59.713 ; 47,59.7 47.125,59.825 47.125,60.075 46.8,60.4 46.8,62.75 46.22,63.33 46.22,65.445 46.46,65.685 49.985,65.685 50.265,65.965 54.44,65.965 54.505,66.03 55.605,66.03 55.74,66.165 55.74,67.515 ; U2.G3@55.485,67.79 55.74,67.535
DDR_DQS1_P: U1.V19 U2.F3 | length 43.2
  Top Layer w0.1: U1.V19@34.97,64.08 34.975,64.08 34.998,64.08 35.033,64.045 35.455,64.045 36.278,63.222 36.278,62.247 37.85,60.675 38.625,60.675 38.895,60.945 39.15,60.945 39.7,60.395 39.7,59.95 39.925,59.725 42.075,59.725 42.325,59.975 43.355,61.005 43.355,63.505 43.45,63.6 43.725,63.6 43.8,63.525 43.8,62.275 43.92,62.155 43.92,61.58 44.255,61.245 44.955,61.245 45.075,61.125 45.075,60.78 44.95,60.655 43.655,60.655 43.275,60.275 43.275,59.7 43.505,59.47 44.67,59.47 44.795,59.595 45.43,59.595 45.55,59.475 45.793,59.475 45.798,59.47 47.12,59.47 47.375,59.725 47.375,60.2 47.03,60.545 47.03,62.845 46.45,63.425 46.45,65.35 46.555,65.455 50.16,65.455 50.44,65.735 54.535,65.735 54.6,65.8 55.7,65.8 55.97,66.07 55.97,67.545 U2.F3@56.25,67.825
DDR_ODT: R27.1 U1.H18 | length 6.8
  Top Layer w0.09: U1.H18@34.47,69.08 34.475,69.08 34.6,69.08 34.68,69.16 35.26,69.16 35.425,69.325 38.8,69.325 39.6,70.125 v1(40.025,70.125)
  Bottom Layer w0.12: v1(40.025,70.125) 40.275,70.125 40.425,70.275 R27.1@40.775,70.275
DDR_RASN: R22.1 U1.1E9 | length 4.9
  Top Layer w0.09: U1.1E9@33.075,68.075 33.37,68.37 33.693,68.37 33.738,68.325 35.45,68.325 35.65,68.525 36.05,68.525 36.15,68.425 37,68.425 37.3,68.125 R22.1@37.3,67.825 ; U1.1E9@33.125,68.025 U1.1E9@33.145,68.045
DDR_RESETN: R32.2 U1.C16 U2.T2 | length 26.7
  Top Layer w0.09: U1.C16@33.475,71.575 33.475,71.725 33.23,71.97 33.23,72.176 33.384,72.33 33.576,72.33 33.725,72.479 33.725,73.775 36.25,76.3 v1@47.7,76.3 ; v1@47.775,76.325 47.9,76.45 R32.2@48.4,76.45
  Top Layer w0.12: v1(47.75,69.925) 47.75,69.4 48.25,68.9 U2.T2@48.25,68.625
  Bottom Layer w0.12: v1@47.725,69.925 47.725,70.925 48.375,71.575 48.375,72.156 47.725,72.806 v1(47.725,76.3)
DDR_WEN: R26.1 U1.J18 | length 5.9
  Top Layer w0.09: U1.J18@34.47,68.58 34.475,68.58 34.634,68.58 34.874,68.82 35.405,68.82 35.51,68.925 38.175,68.925 38.7,68.4 39.95,68.4 R26.1@40.025,68.475
eMMC_SDIO2_D0: U1.1A4 U5.A3 | length 15.5
  Top Layer w0.09: v1(29.3,71.15) 29.8,70.65 29.825,70.625 29.875,70.625 U1.1A4@29.875,70.645 ; U5.A3@30.65,84.475 30.65,84.2 31.188,83.662 31.188,83.087
  Top Layer w0.13: v1(29.75,75.475) 31.65,77.375 31.65,82.625 31.188,83.087
  Bottom Layer w0.13: v1(29.3,71.15) 29.3,71.725 29.475,71.9 29.475,73.575 29.75,73.85 v1(29.75,75.475)
eMMC_SDIO2_D1: U1.C8 U5.A4 | length 14.7
  Top Layer w0.09: U1.C8@29.475,71.575 29.8,71.25 v1(29.8,71.15) ; U5.A4@30.15,84.475 30.15,83.95 30.475,83.625 30.475,83.25
  Top Layer w0.13: v1(30.2,77.025) 30.95,77.775 30.95,82.275 30.475,82.75 30.475,83.25
  Bottom Layer w0.09: 30.175,73.15 30.2,73.175
  Bottom Layer w0.13: v1@29.825,71.15 29.825,72.8 30.175,73.15 ; 30.2,73.175 v1(30.2,77.025)
eMMC_SDIO2_D2: U1.C7 U5.A5 | length 14.2
  Top Layer w0.09: 28.525,74.4 28.525,73.775 28.875,73.425 28.875,72.975 28.725,72.825 28.725,71.815 28.965,71.575 U1.C7@28.975,71.575 ; U5.A5@29.65,84.475 29.65,83.725 29.775,83.6 29.775,83.25
  Top Layer w0.13: 28.525,74.4 28.525,75.85 29.35,76.675 29.35,77.425 30.25,78.325 30.25,81.75 29.775,82.225 29.775,83.25
eMMC_SDIO2_D3: U1.B6 U5.B2 | length 16.3
  Top Layer w0.09: 28.275,73.85 28.275,73.55 28.17,73.445 28.17,73.059 28.23,72.999 28.23,72.474 28.374,72.33 28.425,72.33 28.475,72.28 U1.B6@28.475,72.075 ; 28.7,83.6 28.7,84.125 28.9,84.325 28.9,85.064 29.061,85.225 30.9,85.225 U5.B2@31.15,84.975
  Top Layer w0.13: 28.275,73.85 28.275,74.525 28,74.8 28,75.825 29,76.825 29,83.3 28.7,83.6
eMMC_SDIO2_D4: U1.B8 U5.B3 | length 14.5
  Top Layer w0.09: U1.B8@29.475,72.075 29.56,72.16 29.56,74.535 29.725,74.7 29.725,74.9 ; U5.B3@30.65,84.975 30.65,84.965 30.9,84.715 30.9,84.386 31.5,83.786 31.5,83.275
  Top Layer w0.13: 29.725,74.9 32,77.175 32,82.775 31.5,83.275
eMMC_SDIO2_D5: U1.C9 U5.B4 | length 15.3
  Top Layer w0.09: 29.39,74.71 29.39,72.336 29.23,72.176 29.23,71.95 29.355,71.825 29.725,71.825 U1.C9@29.975,71.575 ; U5.B4@30.15,84.975 30.4,84.725 30.4,84.05 30.85,83.6 30.85,83.25
  Top Layer w0.1: 29.39,74.71 29.39,75.665
  Top Layer w0.13: 29.39,75.665 31.3,77.575 31.3,82.45 30.85,82.9 30.85,83.25
eMMC_SDIO2_D6: U1.B7 U5.B5 | length 14.2
  Top Layer w0.09: 28.925,74.715 29.22,74.42 29.22,72.445 28.975,72.2 U1.B7@28.975,72.075 ; U5.B5@29.65,84.975 29.65,84.965 29.89,84.725 29.89,83.86 30.1,83.65 30.1,83.25
  Top Layer w0.13: 28.925,74.715 28.925,75.725 29.7,76.5 29.7,77.166 30.6,78.066 30.6,82.05 30.1,82.55 30.1,83.25
eMMC_SDIO2_D7: U1.C10 U5.B6 | length 16.9
  Top Layer w0.09: U5.B6@29.15,84.975 29.4,84.725 v1(29.4,83.45) ; U1.C10@30.475,71.575 30.72,71.82 30.72,74.02
  Top Layer w0.13: 30.72,74.02 32.35,75.65 32.35,82.95 v1(31.85,83.45)
  Bottom Layer w0.09: v1(29.4,83.45) v1(31.85,83.45)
